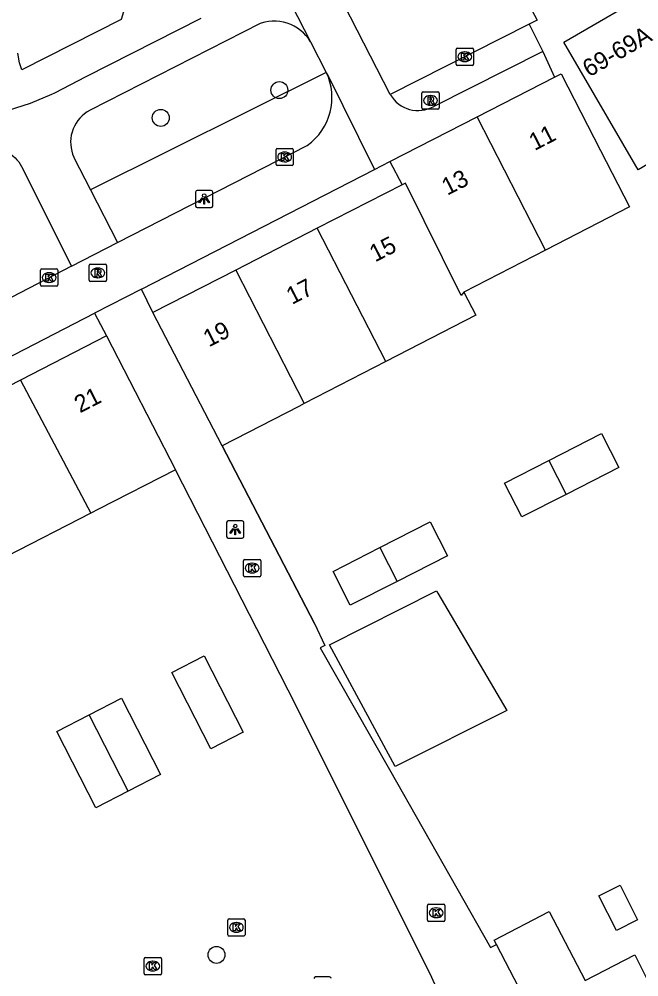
# Model space of a CAD drawing. Extents: x 160379 to 161131, y 383940 to 384849.
# Drawn here: x 161029.9 to 161065.7, y 384084.7 to 384140 of the extents above; entities that cross this region are included whole.
import ezdxf

# ---------------------------------------------------------------- set-up
doc = ezdxf.new("R2010")
doc.units = 0
for name, color, linetype in [('IMGEO_Boom', 7, 'Continuous'), ('IMGEO_Groenvoorziening', 7, 'Continuous'), ('IMGEO_Kolk', 7, 'Continuous'), ('IMGEO_Lichtpunt', 7, 'Continuous'), ('IMGEO_Muur', 7, 'Continuous'), ('IMGEO_Pand', 7, 'Continuous'), ('IMGEO_Pand_nummerreeks', 7, 'Continuous'), ('IMGEO_Parkeervlak_open', 7, 'Continuous'), ('IMGEO_Rijbaan_lokaal_open', 7, 'Continuous'), ('IMGEO_Rioolput', 7, 'Continuous'), ('IMGEO_Voetpad_halfverhard', 7, 'Continuous'), ('IMGEO_Voetpad_open', 7, 'Continuous')]:
    doc.layers.add(name, color=color, linetype=linetype)

msp = doc.modelspace()

# ---------------------------------------------------------------- linework, layer by layer
at = {"layer": 'IMGEO_Boom'}
for centre in [(161044.919, 384135.947), (161038.059, 384134.34), (161041.285, 384085.952)]:
    msp.add_circle(centre, 0.489, dxfattribs=at)
at = {"layer": 'IMGEO_Groenvoorziening'}
for points in [[(161036.447, 384142.278), (161035.775, 384140.036), (161030.032, 384137.124), (161029.891, 384137.526), (161029.797, 384138.079)], [(161047.633, 384136.971), (161033.998, 384130.18)]]:
    msp.add_lwpolyline(points, dxfattribs=at)
at = {"layer": 'IMGEO_Kolk'}
for p, q in [((161055.138, 384137.447), (161055.138, 384138.299)), ((161055.213, 384138.373), (161056.065, 384138.373)), ((161055.626, 384138.153), (161055.651, 384138.153)), ((161056.139, 384138.299), (161056.139, 384137.447)), ((161055.649, 384137.593), (161055.624, 384137.593)), ((161056.065, 384137.373), (161055.213, 384137.373)), ((161044.725, 384131.653), (161044.725, 384132.505)), ((161044.8, 384132.579), (161045.652, 384132.579)), ((161045.726, 384132.505), (161045.726, 384131.653)), ((161045.213, 384132.359), (161045.238, 384132.359)), ((161045.652, 384131.579), (161044.8, 384131.579)), ((161045.236, 384131.799), (161045.211, 384131.799)), ((161031.104, 384124.679), (161031.104, 384125.531)), ((161031.179, 384125.605), (161032.031, 384125.605)), ((161031.592, 384125.385), (161031.617, 384125.385)), ((161032.105, 384125.531), (161032.105, 384124.679)), ((161031.615, 384124.825), (161031.59, 384124.825)), ((161032.031, 384124.605), (161031.179, 384124.605)), ((161042.842, 384107.89), (161042.842, 384108.742)), ((161042.917, 384108.816), (161043.769, 384108.816)), ((161043.33, 384108.596), (161043.355, 384108.596)), ((161043.843, 384108.742), (161043.843, 384107.89)), ((161043.353, 384108.036), (161043.328, 384108.036)), ((161043.769, 384107.816), (161042.917, 384107.816)), ((161053.487, 384087.959), (161053.487, 384088.811)), ((161053.562, 384088.885), (161054.414, 384088.885)), ((161053.975, 384088.665), (161054, 384088.665)), ((161054.488, 384088.811), (161054.488, 384087.959)), ((161053.998, 384088.105), (161053.973, 384088.105)), ((161041.933, 384087.118), (161041.933, 384087.97)), ((161042.008, 384088.044), (161042.86, 384088.044)), ((161042.421, 384087.824), (161042.446, 384087.824)), ((161042.934, 384087.97), (161042.934, 384087.118)), ((161054.414, 384087.885), (161053.562, 384087.885)), ((161042.86, 384087.044), (161042.008, 384087.044)), ((161042.444, 384087.264), (161042.419, 384087.264)), ((161037.096, 384084.878), (161037.096, 384085.73)), ((161037.171, 384085.804), (161038.023, 384085.804)), ((161037.584, 384085.584), (161037.609, 384085.584)), ((161038.097, 384085.73), (161038.097, 384084.878)), ((161038.023, 384084.804), (161037.171, 384084.804)), ((161037.607, 384085.024), (161037.582, 384085.024))]:
    msp.add_line(p, q, dxfattribs=at)
for points in [[(161055.138, 384137.447), (161055.138, 384138.299)], [(161055.213, 384138.373), (161056.065, 384138.373)], [(161055.459, 384138.073), (161055.582, 384138.073), (161055.582, 384137.922), (161055.712, 384138.073), (161055.876, 384138.073), (161055.73, 384137.922), (161055.883, 384137.673), (161055.731, 384137.673), (161055.646, 384137.837), (161055.582, 384137.77), (161055.582, 384137.673), (161055.459, 384137.673), (161055.459, 384138.073)], [(161056.139, 384138.299), (161056.139, 384137.447)], [(161056.065, 384137.373), (161055.213, 384137.373)], [(161044.725, 384131.653), (161044.725, 384132.505)], [(161044.8, 384132.579), (161045.652, 384132.579)], [(161045.726, 384132.505), (161045.726, 384131.653)], [(161045.046, 384132.279), (161045.169, 384132.279), (161045.169, 384132.128), (161045.299, 384132.279), (161045.463, 384132.279), (161045.317, 384132.128), (161045.47, 384131.879), (161045.318, 384131.879), (161045.233, 384132.043), (161045.169, 384131.976), (161045.169, 384131.879), (161045.046, 384131.879), (161045.046, 384132.279)], [(161045.652, 384131.579), (161044.8, 384131.579)], [(161031.104, 384124.679), (161031.104, 384125.531)], [(161031.179, 384125.605), (161032.031, 384125.605)], [(161031.425, 384125.305), (161031.548, 384125.305), (161031.548, 384125.154), (161031.678, 384125.305), (161031.842, 384125.305), (161031.696, 384125.154), (161031.849, 384124.905), (161031.697, 384124.905), (161031.612, 384125.069), (161031.548, 384125.002), (161031.548, 384124.905), (161031.425, 384124.905), (161031.425, 384125.305)], [(161032.105, 384125.531), (161032.105, 384124.679)], [(161032.031, 384124.605), (161031.179, 384124.605)], [(161042.842, 384107.89), (161042.842, 384108.742)], [(161042.917, 384108.816), (161043.769, 384108.816)], [(161043.843, 384108.742), (161043.843, 384107.89)], [(161043.163, 384108.516), (161043.286, 384108.516), (161043.286, 384108.365), (161043.416, 384108.516), (161043.58, 384108.516), (161043.434, 384108.365), (161043.587, 384108.116), (161043.435, 384108.116), (161043.35, 384108.28), (161043.286, 384108.213), (161043.286, 384108.116), (161043.163, 384108.116), (161043.163, 384108.516)], [(161043.769, 384107.816), (161042.917, 384107.816)], [(161053.487, 384087.959), (161053.487, 384088.811)], [(161053.562, 384088.885), (161054.414, 384088.885)], [(161054.488, 384088.811), (161054.488, 384087.959)], [(161053.808, 384088.585), (161053.931, 384088.585), (161053.931, 384088.434), (161054.061, 384088.585), (161054.225, 384088.585), (161054.079, 384088.434), (161054.232, 384088.185), (161054.08, 384088.185), (161053.995, 384088.349), (161053.931, 384088.282), (161053.931, 384088.185), (161053.808, 384088.185), (161053.808, 384088.585)], [(161041.933, 384087.118), (161041.933, 384087.97)], [(161042.008, 384088.044), (161042.86, 384088.044)], [(161042.254, 384087.744), (161042.377, 384087.744), (161042.377, 384087.593), (161042.507, 384087.744), (161042.671, 384087.744), (161042.525, 384087.593), (161042.678, 384087.344), (161042.526, 384087.344), (161042.441, 384087.508), (161042.377, 384087.441), (161042.377, 384087.344), (161042.254, 384087.344), (161042.254, 384087.744)], [(161042.934, 384087.97), (161042.934, 384087.118)], [(161054.414, 384087.885), (161053.562, 384087.885)], [(161042.86, 384087.044), (161042.008, 384087.044)], [(161037.096, 384084.878), (161037.096, 384085.73)], [(161037.171, 384085.804), (161038.023, 384085.804)], [(161037.417, 384085.504), (161037.54, 384085.504), (161037.54, 384085.353), (161037.67, 384085.504), (161037.834, 384085.504), (161037.688, 384085.353), (161037.841, 384085.104), (161037.689, 384085.104), (161037.604, 384085.268), (161037.54, 384085.201), (161037.54, 384085.104), (161037.417, 384085.104), (161037.417, 384085.504)], [(161038.097, 384085.73), (161038.097, 384084.878)], [(161038.023, 384084.804), (161037.171, 384084.804)]]:
    msp.add_lwpolyline(points, dxfattribs=at)
for centre, start, end in [((161055.215, 384138.297), 91.552, 178.448), ((161055.215, 384138.297), 91.552, 178.448), ((161056.063, 384138.297), 1.552, 88.448), ((161056.063, 384138.297), 1.552, 88.448), ((161055.215, 384137.449), 181.552, 268.448), ((161055.215, 384137.449), 181.552, 268.448), ((161056.063, 384137.449), 271.552, 358.448), ((161056.063, 384137.449), 271.552, 358.448), ((161044.802, 384132.503), 91.552, 178.448), ((161044.802, 384132.503), 91.552, 178.448), ((161045.65, 384132.503), 1.552, 88.448), ((161045.65, 384132.503), 1.552, 88.448), ((161044.802, 384131.655), 181.552, 268.448), ((161044.802, 384131.655), 181.552, 268.448), ((161045.65, 384131.655), 271.552, 358.448), ((161045.65, 384131.655), 271.552, 358.448), ((161031.181, 384125.529), 91.552, 178.448), ((161031.181, 384125.529), 91.552, 178.448), ((161032.029, 384125.529), 1.552, 88.448), ((161032.029, 384125.529), 1.552, 88.448), ((161031.181, 384124.681), 181.552, 268.448), ((161031.181, 384124.681), 181.552, 268.448), ((161032.029, 384124.681), 271.552, 358.448), ((161032.029, 384124.681), 271.552, 358.448), ((161042.919, 384108.74), 91.552, 178.448), ((161042.919, 384108.74), 91.552, 178.448), ((161043.767, 384108.74), 1.552, 88.448), ((161043.767, 384108.74), 1.552, 88.448), ((161042.919, 384107.892), 181.552, 268.448), ((161042.919, 384107.892), 181.552, 268.448), ((161043.767, 384107.892), 271.552, 358.448), ((161043.767, 384107.892), 271.552, 358.448), ((161053.564, 384088.809), 91.552, 178.448), ((161053.564, 384088.809), 91.552, 178.448), ((161054.412, 384088.809), 1.552, 88.448), ((161054.412, 384088.809), 1.552, 88.448), ((161042.01, 384087.968), 91.552, 178.448), ((161042.01, 384087.968), 91.552, 178.448), ((161042.858, 384087.968), 1.552, 88.448), ((161042.858, 384087.968), 1.552, 88.448), ((161053.564, 384087.961), 181.552, 268.448), ((161053.564, 384087.961), 181.552, 268.448), ((161054.412, 384087.961), 271.552, 358.448), ((161054.412, 384087.961), 271.552, 358.448), ((161042.01, 384087.12), 181.552, 268.448), ((161042.01, 384087.12), 181.552, 268.448), ((161042.858, 384087.12), 271.552, 358.448), ((161042.858, 384087.12), 271.552, 358.448), ((161037.173, 384085.728), 91.552, 178.448), ((161037.173, 384085.728), 91.552, 178.448), ((161038.021, 384085.728), 1.552, 88.448), ((161038.021, 384085.728), 1.552, 88.448), ((161037.173, 384084.88), 181.552, 268.448), ((161037.173, 384084.88), 181.552, 268.448), ((161038.021, 384084.88), 271.552, 358.448), ((161038.021, 384084.88), 271.552, 358.448)]:
    msp.add_arc(centre, 0.0765, start, end, dxfattribs=at)
for centre, major_axis, ratio, start_param, end_param in [((161055.625, 384137.873), (-0.387, 0.002), 0.722429, 4.712389, 7.853982), ((161055.65, 384137.873), (-0.39, 0.002), 0.717154, 1.570796, 4.712389), ((161045.212, 384132.079), (-0.387, 0.002), 0.722429, 4.712389, 7.853982), ((161045.237, 384132.079), (-0.39, 0.002), 0.717154, 1.570796, 4.712389), ((161031.591, 384125.105), (-0.387, 0.002), 0.722429, 4.712389, 7.853982), ((161031.616, 384125.105), (-0.39, 0.002), 0.717154, 1.570796, 4.712389), ((161043.329, 384108.316), (-0.387, 0.002), 0.722429, 4.712389, 7.853982), ((161043.354, 384108.316), (-0.39, 0.002), 0.717154, 1.570796, 4.712389), ((161053.974, 384088.385), (-0.387, 0.002), 0.722429, 4.712389, 7.853982), ((161053.999, 384088.385), (-0.39, 0.002), 0.717154, 1.570796, 4.712389), ((161042.42, 384087.544), (-0.387, 0.002), 0.722429, 4.712389, 7.853982), ((161042.445, 384087.544), (-0.39, 0.002), 0.717154, 1.570796, 4.712389), ((161037.583, 384085.304), (-0.387, 0.002), 0.722429, 4.712389, 7.853982), ((161037.608, 384085.304), (-0.39, 0.002), 0.717154, 1.570796, 4.712389)]:
    msp.add_ellipse(centre, major_axis=major_axis, ratio=ratio, start_param=start_param, end_param=end_param, dxfattribs=at)
at = {"layer": 'IMGEO_Lichtpunt'}
for p, q in [((161040.074, 384130.052), (161040.074, 384129.245)), ((161040.074, 384130.052), (161040.074, 384129.245)), ((161040.976, 384130.147), (161040.168, 384130.147)), ((161040.976, 384130.147), (161040.168, 384130.147)), ((161041.07, 384129.245), (161041.07, 384130.052)), ((161041.07, 384129.245), (161041.07, 384130.052)), ((161040.168, 384129.151), (161040.976, 384129.151)), ((161040.168, 384129.151), (161040.976, 384129.151)), ((161041.868, 384110.948), (161041.868, 384110.141)), ((161041.868, 384110.948), (161041.868, 384110.141)), ((161042.77, 384111.043), (161041.962, 384111.043)), ((161042.77, 384111.043), (161041.962, 384111.043)), ((161042.864, 384110.141), (161042.864, 384110.948)), ((161042.864, 384110.141), (161042.864, 384110.948)), ((161041.962, 384110.047), (161042.77, 384110.047)), ((161041.962, 384110.047), (161042.77, 384110.047)), ((161047.82, 384084.684), (161047.012, 384084.684)), ((161047.82, 384084.684), (161047.012, 384084.684))]:
    msp.add_line(p, q, dxfattribs=at)
for points in [[(161040.448, 384129.716), (161040.487, 384129.688), (161040.299, 384129.426), (161040.261, 384129.453), (161040.448, 384129.716)], [(161040.55, 384129.668), (161040.597, 384129.668), (161040.597, 384129.346), (161040.55, 384129.346), (161040.55, 384129.668)], [(161040.66, 384129.688), (161040.698, 384129.715), (161040.885, 384129.453), (161040.846, 384129.425), (161040.66, 384129.688)], [(161042.242, 384110.612), (161042.281, 384110.584), (161042.093, 384110.322), (161042.055, 384110.349), (161042.242, 384110.612)], [(161042.344, 384110.564), (161042.391, 384110.564), (161042.391, 384110.242), (161042.344, 384110.242), (161042.344, 384110.564)], [(161042.454, 384110.584), (161042.492, 384110.611), (161042.679, 384110.349), (161042.64, 384110.321), (161042.454, 384110.584)]]:
    msp.add_lwpolyline(points, dxfattribs=at)
for centre in [(161040.573, 384129.85), (161042.367, 384110.746)]:
    msp.add_circle(centre, 0.0994, dxfattribs=at)
for centre, start, end in [((161040.168, 384130.052), 90, 180), ((161040.168, 384130.052), 90, 180), ((161040.976, 384130.052), 0, 90), ((161040.976, 384130.052), 0, 90), ((161040.168, 384129.245), 180, 270), ((161040.168, 384129.245), 180, 270), ((161040.976, 384129.245), 270, 0), ((161040.976, 384129.245), 270, 360), ((161041.962, 384110.948), 90, 180), ((161041.962, 384110.948), 90, 180), ((161042.77, 384110.948), 0, 90), ((161042.77, 384110.948), 0, 90), ((161041.962, 384110.141), 180, 270), ((161041.962, 384110.141), 180, 270), ((161042.77, 384110.141), 270, 0), ((161042.77, 384110.141), 270, 360), ((161047.012, 384084.589), 90, 180), ((161047.012, 384084.589), 90, 180), ((161047.82, 384084.589), 0, 90), ((161047.82, 384084.589), 0, 90)]:
    msp.add_arc(centre, 0.0946, start, end, dxfattribs=at)
at = {"layer": 'IMGEO_Muur'}
for points in [[(161046.943, 384105.106), (161041.603, 384115.373)], [(161043.612, 384104.8), (161038.91, 384114.001)], [(161051.279, 384096.671), (161057.133, 384086.372), (161057.479, 384086.551)]]:
    msp.add_lwpolyline(points, dxfattribs=at)
at = {"layer": 'IMGEO_Pand'}
for points in [[(161066.822, 384141.894), (161071.122, 384134.527), (161065.667, 384131.342), (161061.366, 384138.709), (161066.822, 384141.894)], [(161060.825, 384136.697), (161061.209, 384136.894), (161063.496, 384132.448), (161065.173, 384129.188), (161060.316, 384126.688)], [(161056.35, 384134.403), (161060.825, 384136.697)], [(161051.315, 384131.821), (161056.35, 384134.403)], [(161060.316, 384126.688), (161056.35, 384134.403)], [(161051.315, 384131.821), (161052.02, 384130.466)], [(161052.02, 384130.466), (161047.111, 384127.956)], [(161055.594, 384124.258), (161055.435, 384124.076), (161052.217, 384130.562), (161052.02, 384130.466)], [(161047.111, 384127.956), (161042.393, 384125.545)], [(161051.074, 384120.247), (161047.111, 384127.956)], [(161060.316, 384126.688), (161055.594, 384124.258)], [(161042.393, 384125.545), (161037.601, 384123.095)], [(161042.393, 384125.545), (161046.362, 384117.822)], [(161055.594, 384124.258), (161056.279, 384122.926), (161051.074, 384120.247)], [(161041.603, 384115.373), (161037.601, 384123.095)], [(161034.932, 384121.732), (161029.948, 384119.18)], [(161034.932, 384121.732), (161038.91, 384114.001)], [(161051.074, 384120.247), (161046.362, 384117.822)], [(161029.948, 384119.18), (161025.064, 384116.68)], [(161029.948, 384119.18), (161034.018, 384111.491)], [(161046.362, 384117.822), (161046.049, 384117.661), (161041.603, 384115.373)], [(161060.5, 384114.534), (161063.552, 384116.09), (161064.55, 384114.129), (161061.496, 384112.572)], [(161061.496, 384112.572), (161058.937, 384111.268), (161057.939, 384113.229), (161060.5, 384114.534)], [(161060.5, 384114.534), (161061.496, 384112.572)], [(161038.91, 384114.001), (161034.462, 384111.719), (161034.018, 384111.491)], [(161034.018, 384111.491), (161029.137, 384108.987)], [(161050.734, 384109.507), (161053.635, 384110.986), (161054.633, 384109.025), (161051.735, 384107.548)], [(161051.735, 384107.548), (161049.02, 384106.164), (161048.022, 384108.125), (161050.734, 384109.507)], [(161050.734, 384109.507), (161051.735, 384107.548)], [(161054.008, 384106.99), (161054.077, 384106.873), (161058.069, 384100.086), (161051.611, 384096.838), (161047.809, 384103.873), (161054.008, 384106.99)], [(161038.696, 384102.28), (161040.565, 384103.238), (161042.822, 384098.824), (161040.953, 384097.866), (161038.696, 384102.28)], [(161033.913, 384099.829), (161035.782, 384100.787), (161038.039, 384096.373), (161036.17, 384095.416)], [(161036.17, 384095.416), (161034.304, 384094.46), (161032.044, 384098.871), (161033.913, 384099.829)], [(161036.17, 384095.416), (161033.913, 384099.829)], [(161065.628, 384087.988), (161064.411, 384087.371), (161063.401, 384089.365), (161064.617, 384089.982), (161065.628, 384087.988)], [(161057.479, 384086.551), (161057.345, 384086.808), (161060.522, 384088.46), (161062.6, 384084.464), (161065.468, 384085.956), (161066.149, 384084.612)], [(161065.206, 384071.687), (161057.479, 384086.551)]]:
    msp.add_lwpolyline(points, dxfattribs=at)
at = {"layer": 'IMGEO_Parkeervlak_open'}
msp.add_lwpolyline([(161059.366, 384139.765), (161060.16, 384138.173)], dxfattribs=at)
at = {"layer": 'IMGEO_Rijbaan_lokaal_open'}
for points in [[(161057.391, 384144.576), (161059.823, 384139.987), (161059.366, 384139.765)], [(161051.334, 384135.69), (161047.13, 384143.894)], [(161059.366, 384139.765), (161051.334, 384135.69)]]:
    msp.add_lwpolyline(points, dxfattribs=at)
at = {"layer": 'IMGEO_Rioolput'}
for p, q in [((161053.16, 384134.92), (161053.16, 384135.772)), ((161053.235, 384135.846), (161054.087, 384135.846)), ((161054.161, 384135.772), (161054.161, 384134.92)), ((161053.648, 384135.626), (161053.673, 384135.626)), ((161054.087, 384134.846), (161053.235, 384134.846)), ((161053.671, 384135.066), (161053.646, 384135.066)), ((161033.918, 384124.951), (161033.918, 384125.803)), ((161033.993, 384125.877), (161034.845, 384125.877)), ((161034.919, 384125.803), (161034.919, 384124.951)), ((161034.406, 384125.657), (161034.431, 384125.657)), ((161034.845, 384124.877), (161033.993, 384124.877)), ((161034.429, 384125.097), (161034.404, 384125.097))]:
    msp.add_line(p, q, dxfattribs=at)
for points in [[(161053.16, 384134.92), (161053.16, 384135.772)], [(161053.235, 384135.846), (161054.087, 384135.846)], [(161054.161, 384135.772), (161054.161, 384134.92)], [(161053.749, 384135.544), (161053.497, 384135.546), (161053.497, 384135.146)], [(161053.497, 384135.146), (161053.621, 384135.146), (161053.621, 384135.308), (161053.632, 384135.308)], [(161053.675, 384135.465), (161053.621, 384135.465), (161053.621, 384135.384)], [(161053.621, 384135.384), (161053.673, 384135.384)], [(161053.679, 384135.279), (161053.75, 384135.146), (161053.89, 384135.146), (161053.825, 384135.272)], [(161054.087, 384134.846), (161053.235, 384134.846)], [(161033.918, 384124.951), (161033.918, 384125.803)], [(161033.993, 384125.877), (161034.845, 384125.877)], [(161034.919, 384125.803), (161034.919, 384124.951)], [(161034.507, 384125.575), (161034.255, 384125.577), (161034.255, 384125.177)], [(161034.255, 384125.177), (161034.379, 384125.177), (161034.379, 384125.339), (161034.39, 384125.339)], [(161034.433, 384125.496), (161034.379, 384125.496), (161034.379, 384125.415)], [(161034.379, 384125.415), (161034.431, 384125.415)], [(161034.437, 384125.31), (161034.508, 384125.177), (161034.648, 384125.177), (161034.583, 384125.303)], [(161034.845, 384124.877), (161033.993, 384124.877)]]:
    msp.add_lwpolyline(points, dxfattribs=at)
for centre, radius, start, end in [((161053.237, 384135.77), 0.0765, 91.552, 178.448), ((161053.237, 384135.77), 0.0765, 91.552, 178.448), ((161054.085, 384135.77), 0.0765, 1.552, 88.448), ((161054.085, 384135.77), 0.0765, 1.552, 88.448), ((161053.631, 384135.255), 0.0533, 26.0293, 88.6989), ((161053.657, 384135.573), 0.19, 274.7715, 282.9687), ((161053.681, 384135.369), 0.0964, 77.0061, 93.1865), ((161053.695, 384135.426), 0.0378, 276.6634, 79.6772), ((161053.748, 384135.434), 0.109, 350.3612, 89.416), ((161053.746, 384135.434), 0.112, 277.5842, 350.9817), ((161053.73, 384135.219), 0.108, 29.5134, 73.7905), ((161053.237, 384134.922), 0.0765, 181.552, 268.448), ((161053.237, 384134.922), 0.0765, 181.552, 268.448), ((161054.085, 384134.922), 0.0765, 271.552, 358.448), ((161054.085, 384134.922), 0.0765, 271.552, 358.448), ((161033.995, 384125.801), 0.0765, 91.552, 178.448), ((161033.995, 384125.801), 0.0765, 91.552, 178.448), ((161034.843, 384125.801), 0.0765, 1.552, 88.448), ((161034.843, 384125.801), 0.0765, 1.552, 88.448), ((161034.389, 384125.286), 0.0533, 26.0293, 88.6989), ((161034.415, 384125.604), 0.19, 274.7715, 282.9687), ((161034.439, 384125.4), 0.0964, 77.0061, 93.1865), ((161034.453, 384125.457), 0.0378, 276.6634, 79.6772), ((161034.506, 384125.465), 0.109, 350.3612, 89.416), ((161034.504, 384125.465), 0.112, 277.5842, 350.9817), ((161034.488, 384125.25), 0.108, 29.5134, 73.7905), ((161033.995, 384124.953), 0.0765, 181.552, 268.448), ((161033.995, 384124.953), 0.0765, 181.552, 268.448), ((161034.843, 384124.953), 0.0765, 271.552, 358.448), ((161034.843, 384124.953), 0.0765, 271.552, 358.448)]:
    msp.add_arc(centre, radius, start, end, dxfattribs=at)
for centre, major_axis, ratio, start_param, end_param in [((161053.647, 384135.346), (-0.387, 0.002), 0.722429, 4.712389, 7.853982), ((161053.672, 384135.346), (-0.39, 0.002), 0.717154, 1.570796, 4.712389), ((161034.405, 384125.377), (-0.387, 0.002), 0.722429, 4.712389, 7.853982), ((161034.43, 384125.377), (-0.39, 0.002), 0.717154, 1.570796, 4.712389)]:
    msp.add_ellipse(centre, major_axis=major_axis, ratio=ratio, start_param=start_param, end_param=end_param, dxfattribs=at)
at = {"layer": 'IMGEO_Voetpad_halfverhard'}
for points in [[(161040.371, 384140.079), (161033.725, 384136.709), (161031.909, 384135.762), (161031.749, 384135.685), (161030.518, 384135.17), (161029.247, 384134.766), (161027.944, 384134.478), (161023.951, 384133.656), (161018.887, 384131.803), (161012.616, 384129.509), (161011.953, 384131.288), (161006.277, 384131.058), (161005.718, 384129.189)], [(161046.716, 384138.743), (161046.595, 384138.926), (161046.458, 384139.097), (161046.306, 384139.256), (161046.141, 384139.4), (161045.963, 384139.529), (161045.775, 384139.641), (161045.577, 384139.737), (161045.371, 384139.814), (161045.16, 384139.872), (161044.944, 384139.912), (161044.726, 384139.932), (161044.506, 384139.932), (161044.288, 384139.913), (161044.072, 384139.874), (161043.86, 384139.816), (161043.814, 384139.801), (161033.972, 384134.781), (161033.811, 384134.688), (161033.658, 384134.581), (161033.516, 384134.46), (161033.385, 384134.328), (161033.267, 384134.184), (161033.162, 384134.031), (161033.07, 384133.868), (161032.994, 384133.698), (161032.934, 384133.522), (161032.889, 384133.341), (161032.861, 384133.157), (161032.849, 384132.971), (161032.854, 384132.785), (161032.875, 384132.6), (161032.913, 384132.418), (161032.967, 384132.239), (161033.037, 384132.067), (161033.042, 384132.055), (161033.998, 384130.18)], [(161017.635, 384117.933), (161012.392, 384124.721), (161013.929, 384125.926), (161013.27, 384127.709), (161024.349, 384131.847), (161027.956, 384132.471), (161027.993, 384132.48), (161028.152, 384132.509), (161028.312, 384132.525), (161028.473, 384132.525), (161028.634, 384132.511), (161028.792, 384132.483), (161028.948, 384132.441), (161029.099, 384132.386), (161029.245, 384132.317), (161029.383, 384132.235), (161029.514, 384132.141), (161029.636, 384132.036), (161029.748, 384131.92), (161029.85, 384131.795), (161029.94, 384131.661), (161030.017, 384131.52), (161032.896, 384125.768)], [(161033.998, 384130.18), (161035.555, 384127.128)]]:
    msp.add_lwpolyline(points, dxfattribs=at)
at = {"layer": 'IMGEO_Voetpad_open'}
for points in [[(161044.85, 384142.402), (161046.716, 384138.743)], [(161046.716, 384138.743), (161047.633, 384136.971)], [(161060.16, 384138.173), (161053.854, 384135.006)], [(161060.16, 384138.173), (161060.825, 384136.697)], [(161047.633, 384136.971), (161047.664, 384136.926), (161050.415, 384131.358)], [(161035.555, 384127.128), (161046.535, 384132.75)], [(161036.946, 384124.434), (161050.415, 384131.358)], [(161050.415, 384131.358), (161051.315, 384131.821)], [(161032.896, 384125.768), (161035.555, 384127.128)], [(161032.896, 384125.768), (161027.949, 384123.209), (161017.635, 384117.933)], [(161036.946, 384124.434), (161034.221, 384123.045)], [(161037.601, 384123.095), (161036.946, 384124.434)], [(161015.1, 384113.176), (161034.221, 384123.045)], [(161034.221, 384123.045), (161034.932, 384121.732)], [(161041.603, 384115.373), (161046.943, 384105.106), (161047.557, 384103.835), (161047.283, 384103.702), (161051.279, 384096.671), (161057.133, 384086.372), (161057.479, 384086.551)], [(161060.623, 384069.375), (161053.635, 384084.865), (161050.608, 384090.89), (161045.881, 384100.391), (161043.612, 384104.8), (161038.91, 384114.001)]]:
    msp.add_lwpolyline(points, dxfattribs=at)
for centre, radius, start, end in [((161044.568, 384135.515), 3.393, 305.4298, 25.408), ((161052.939, 384136.618), 1.854, 210.0376, 299.5907)]:
    msp.add_arc(centre, radius, start, end, dxfattribs=at)

# ---------------------------------------------------------------- texts
at = {"layer": 'IMGEO_Pand_nummerreeks'}
for s, rotation, p in [('69-69A', 30.2751, (161062.828, 384136.668)), ('11', 27.1458, (161059.679, 384132.424)), ('13', 27.1458, (161054.631, 384129.836)), ('15', 27.0761, (161050.455, 384125.982)), ('17', 27.0761, (161045.649, 384123.525)), ('19', 27.0761, (161040.842, 384121.068)), ('21', 27.1119, (161033.388, 384117.257))]:
    msp.add_text(s, height=1, rotation=rotation, dxfattribs=at).set_placement(p)

doc.saveas('drawing.dxf')
